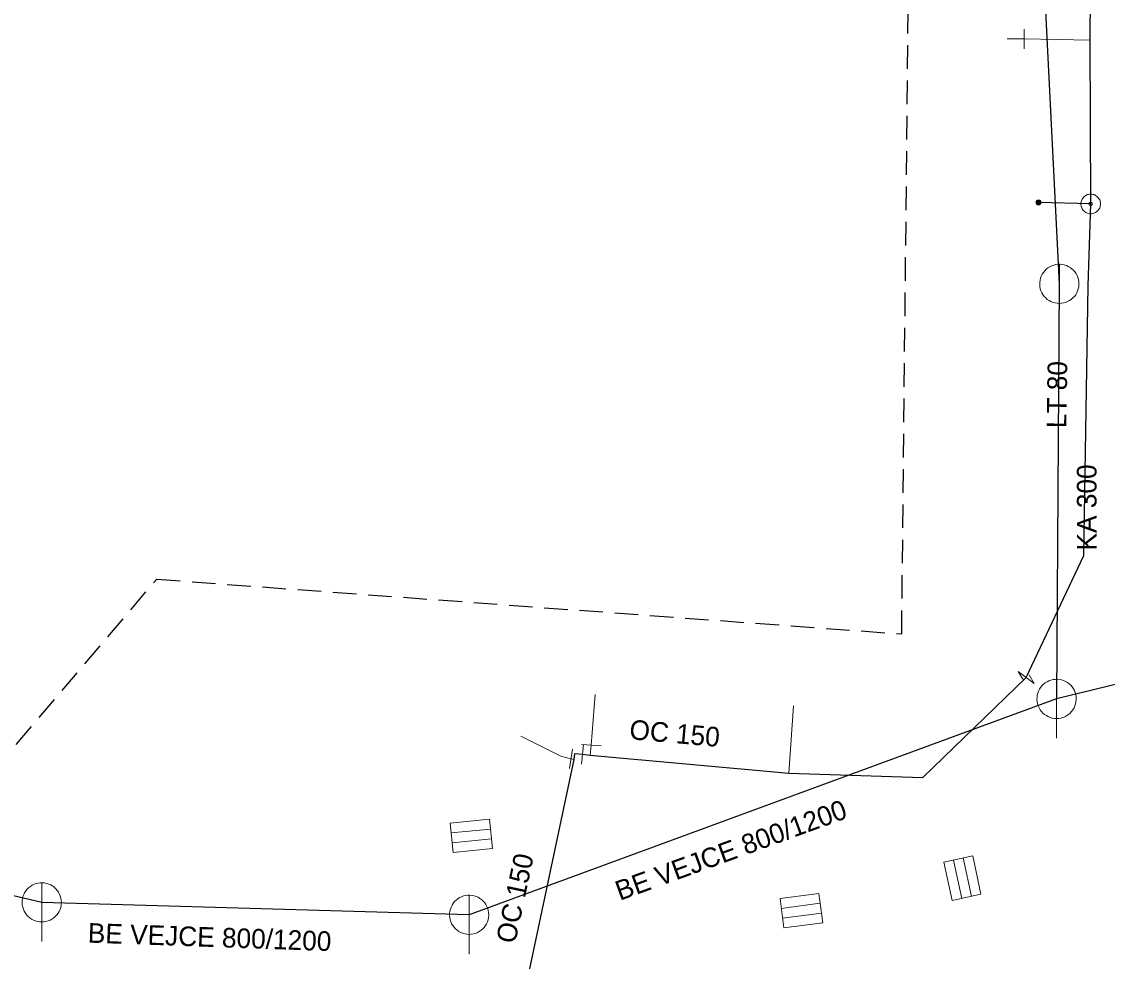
# Model space of a CAD drawing. Extents: x -725643 to -725418, y -978375 to -978221.
# Drawn here: x -725502 to -725446.7, y -978340.9 to -978293 of the extents above; entities that cross this region are included whole.
import ezdxf

# ---------------------------------------------------------------- set-up
doc = ezdxf.new("R2010")
doc.units = 0
doc.header["$LTSCALE"] = 0.4
doc.linetypes.add('MEDIUM_DASHED', pattern=[4.5, 3, -1.5])
doc.layers.add('1', color=7, linetype='Continuous')
for name, color, linetype, lineweight in [('13', 7, 'Continuous', 13), ('14', 7, 'Continuous', 25), ('17', 7, 'Continuous', 25), ('22', 7, 'Continuous', 13), ('34', 7, 'Continuous', 13), ('47', 7, 'Continuous', 13), ('63', 7, 'MEDIUM_DASHED', 25), ('9', 7, 'Continuous', 13)]:
    doc.layers.add(name, color=color, linetype=linetype, lineweight=lineweight)

msp = doc.modelspace()

# ---------------------------------------------------------------- linework, layer by layer
at = {"layer": '13'}
for p, q in [((-725450.884, -978293.877), (-725451.759, -978293.873)), ((-725447.519, -978293.935), (-725450.884, -978293.877)), ((-725462.878, -978331.295), (-725462.639, -978327.859))]:
    msp.add_line(p, q, dxfattribs=at)
for points in [[(-725473.014, -978330.373), (-725472.951, -978329.869), (-725472.749, -978327.278)], [(-725473.986, -978330.566), (-725474.5, -978330.421), (-725476.532, -978329.406)]]:
    msp.add_lwpolyline(points, dxfattribs=at)
at = {"layer": '14'}
for p, q in [((-725450.636, -978276.041), (-725449.097, -978306.355)), ((-725449.097, -978306.355), (-725449.237, -978327.509)), ((-725418.473, -978319.91), (-725449.237, -978327.509))]:
    msp.add_line(p, q, dxfattribs=at)
at = {"layer": '14', "lineweight": 13}
msp.add_line((-725473.829, -978330.592), (-725473.986, -978330.566), dxfattribs=at)
at = {"layer": '14'}
for points in [[(-725449.237, -978327.509), (-725479.175, -978338.51), (-725500.956, -978337.877)], [(-725500.956, -978337.877), (-725523.136, -978332.647), (-725524.855, -978332.647), (-725526.213, -978332.919), (-725527.118, -978333.688), (-725527.513, -978334.331)]]:
    msp.add_lwpolyline(points, dxfattribs=at)
at = {"layer": '17'}
for points in [[(-725447.498, -978302.284), (-725447.519, -978293.935), (-725447.498, -978289.33), (-725447.528, -978279.514), (-725448.234, -978269.846), (-725448.21, -978267.82), (-725448.151, -978262.699), (-725445.719, -978241.531), (-725443.089, -978227.013), (-725441.23, -978223.25), (-725440.059, -978221.699), (-725439.43, -978221.1), (-725439.089, -978220.568)], [(-725450.783, -978326.417), (-725447.845, -978320.194), (-725447.621, -978306.459), (-725447.498, -978302.284), (-725450.158, -978302.21)], [(-725473.397, -978330.332), (-725473.013, -978330.373), (-725462.877, -978331.295), (-725456.052, -978331.515), (-725450.783, -978326.417)], [(-725476.724, -978344.299), (-725473.829, -978330.592), (-725473.78, -978330.284), (-725473.397, -978330.332)]]:
    msp.add_lwpolyline(points, dxfattribs=at)
at = {"layer": '22'}
for p, q in [((-725449.097, -978308.355), (-725449.096, -978305.355)), ((-725449.237, -978329.509), (-725449.236, -978326.509)), ((-725480.082, -978334.342), (-725478.092, -978334.141)), ((-725480.032, -978334.84), (-725478.042, -978334.638)), ((-725454.489, -978335.722), (-725454.069, -978337.678)), ((-725454, -978335.617), (-725453.58, -978337.573)), ((-725500.956, -978339.877), (-725500.955, -978336.877)), ((-725479.175, -978340.51), (-725479.174, -978337.51)), ((-725463.265, -978338.184), (-725461.282, -978337.925)), ((-725463.201, -978338.68), (-725461.217, -978338.421))]:
    msp.add_line(p, q, dxfattribs=at)
for points in [[(-725448.097, -978306.355), (-725448.102, -978306.246), (-725448.12, -978306.138), (-725448.15, -978306.032), (-725448.19, -978305.931), (-725448.242, -978305.834), (-725448.304, -978305.744), (-725448.376, -978305.661), (-725448.456, -978305.587), (-725448.544, -978305.521), (-725448.638, -978305.466), (-725448.738, -978305.421), (-725448.843, -978305.388), (-725448.95, -978305.366), (-725449.059, -978305.356), (-725449.169, -978305.358), (-725449.277, -978305.372), (-725449.384, -978305.397), (-725449.487, -978305.434), (-725449.585, -978305.483), (-725449.677, -978305.541), (-725449.763, -978305.61), (-725449.84, -978305.687), (-725449.909, -978305.773), (-725449.968, -978305.865), (-725450.016, -978305.963), (-725450.053, -978306.066), (-725450.079, -978306.173), (-725450.093, -978306.281), (-725450.096, -978306.391), (-725450.086, -978306.5), (-725450.065, -978306.607), (-725450.031, -978306.711), (-725449.987, -978306.811), (-725449.932, -978306.906), (-725449.866, -978306.994), (-725449.792, -978307.074), (-725449.709, -978307.146), (-725449.619, -978307.208), (-725449.523, -978307.26), (-725449.421, -978307.301), (-725449.316, -978307.331), (-725449.208, -978307.349), (-725449.098, -978307.355), (-725448.989, -978307.349), (-725448.881, -978307.331), (-725448.776, -978307.302), (-725448.674, -978307.261), (-725448.577, -978307.209), (-725448.487, -978307.147), (-725448.404, -978307.076), (-725448.329, -978306.996), (-725448.264, -978306.908), (-725448.208, -978306.814), (-725448.164, -978306.714), (-725448.13, -978306.61), (-725448.108, -978306.502), (-725448.098, -978306.393)], [(-725448.237, -978327.509), (-725448.242, -978327.4), (-725448.26, -978327.292), (-725448.29, -978327.186), (-725448.33, -978327.085), (-725448.382, -978326.988), (-725448.444, -978326.898), (-725448.516, -978326.815), (-725448.596, -978326.741), (-725448.684, -978326.675), (-725448.778, -978326.62), (-725448.878, -978326.575), (-725448.983, -978326.542), (-725449.09, -978326.52), (-725449.199, -978326.51), (-725449.309, -978326.512), (-725449.417, -978326.526), (-725449.524, -978326.551), (-725449.627, -978326.588), (-725449.725, -978326.637), (-725449.817, -978326.695), (-725449.903, -978326.764), (-725449.98, -978326.841), (-725450.049, -978326.927), (-725450.108, -978327.019), (-725450.156, -978327.117), (-725450.193, -978327.22), (-725450.219, -978327.327), (-725450.233, -978327.435), (-725450.236, -978327.545), (-725450.226, -978327.654), (-725450.205, -978327.761), (-725450.171, -978327.865), (-725450.127, -978327.965), (-725450.072, -978328.06), (-725450.006, -978328.148), (-725449.932, -978328.228), (-725449.849, -978328.3), (-725449.759, -978328.362), (-725449.663, -978328.414), (-725449.561, -978328.455), (-725449.456, -978328.485), (-725449.348, -978328.503), (-725449.238, -978328.509), (-725449.129, -978328.503), (-725449.021, -978328.485), (-725448.916, -978328.456), (-725448.814, -978328.415), (-725448.717, -978328.363), (-725448.627, -978328.301), (-725448.544, -978328.23), (-725448.469, -978328.15), (-725448.404, -978328.062), (-725448.348, -978327.968), (-725448.304, -978327.868), (-725448.27, -978327.764), (-725448.248, -978327.656), (-725448.238, -978327.547)], [(-725480.133, -978333.845), (-725478.143, -978333.643), (-725477.992, -978335.135), (-725479.981, -978335.337)], [(-725453.511, -978335.512), (-725453.091, -978337.468), (-725454.558, -978337.783), (-725454.978, -978335.827)], [(-725499.956, -978337.877), (-725499.961, -978337.768), (-725499.979, -978337.66), (-725500.009, -978337.554), (-725500.049, -978337.453), (-725500.101, -978337.356), (-725500.163, -978337.266), (-725500.235, -978337.183), (-725500.315, -978337.109), (-725500.403, -978337.043), (-725500.497, -978336.988), (-725500.597, -978336.943), (-725500.702, -978336.91), (-725500.809, -978336.888), (-725500.918, -978336.878), (-725501.028, -978336.88), (-725501.136, -978336.894), (-725501.243, -978336.919), (-725501.346, -978336.956), (-725501.444, -978337.005), (-725501.536, -978337.063), (-725501.622, -978337.132), (-725501.699, -978337.209), (-725501.768, -978337.295), (-725501.827, -978337.387), (-725501.875, -978337.485), (-725501.912, -978337.588), (-725501.938, -978337.695), (-725501.952, -978337.803), (-725501.955, -978337.913), (-725501.945, -978338.022), (-725501.924, -978338.129), (-725501.89, -978338.233), (-725501.846, -978338.333), (-725501.791, -978338.428), (-725501.725, -978338.516), (-725501.651, -978338.596), (-725501.568, -978338.668), (-725501.478, -978338.73), (-725501.382, -978338.782), (-725501.28, -978338.823), (-725501.175, -978338.853), (-725501.067, -978338.871), (-725500.957, -978338.877), (-725500.848, -978338.871), (-725500.74, -978338.853), (-725500.635, -978338.824), (-725500.533, -978338.783), (-725500.436, -978338.731), (-725500.346, -978338.669), (-725500.263, -978338.598), (-725500.188, -978338.518), (-725500.123, -978338.43), (-725500.067, -978338.336), (-725500.023, -978338.236), (-725499.989, -978338.132), (-725499.967, -978338.024), (-725499.957, -978337.915)], [(-725478.175, -978338.51), (-725478.18, -978338.401), (-725478.198, -978338.293), (-725478.228, -978338.187), (-725478.268, -978338.086), (-725478.32, -978337.989), (-725478.382, -978337.899), (-725478.454, -978337.816), (-725478.534, -978337.742), (-725478.622, -978337.676), (-725478.716, -978337.621), (-725478.816, -978337.576), (-725478.921, -978337.543), (-725479.028, -978337.521), (-725479.137, -978337.511), (-725479.247, -978337.513), (-725479.355, -978337.527), (-725479.462, -978337.552), (-725479.565, -978337.589), (-725479.663, -978337.638), (-725479.755, -978337.696), (-725479.841, -978337.765), (-725479.918, -978337.842), (-725479.987, -978337.928), (-725480.046, -978338.02), (-725480.094, -978338.118), (-725480.131, -978338.221), (-725480.157, -978338.328), (-725480.171, -978338.436), (-725480.174, -978338.546), (-725480.164, -978338.655), (-725480.143, -978338.762), (-725480.109, -978338.866), (-725480.065, -978338.966), (-725480.01, -978339.061), (-725479.944, -978339.149), (-725479.87, -978339.229), (-725479.787, -978339.301), (-725479.697, -978339.363), (-725479.601, -978339.415), (-725479.499, -978339.456), (-725479.394, -978339.486), (-725479.286, -978339.504), (-725479.176, -978339.51), (-725479.067, -978339.504), (-725478.959, -978339.486), (-725478.854, -978339.457), (-725478.752, -978339.416), (-725478.655, -978339.364), (-725478.565, -978339.302), (-725478.482, -978339.231), (-725478.407, -978339.151), (-725478.342, -978339.063), (-725478.286, -978338.969), (-725478.242, -978338.869), (-725478.208, -978338.765), (-725478.186, -978338.657), (-725478.176, -978338.548)], [(-725463.33, -978337.688), (-725461.347, -978337.429), (-725461.153, -978338.917), (-725463.136, -978339.175)]]:
    msp.add_lwpolyline(points, close=True, dxfattribs=at)
at = {"layer": '34'}
for p, q in [((-725450.881, -978293.377), (-725450.887, -978294.376)), ((-725473.91, -978330.071), (-725474.062, -978331.06)), ((-725473.449, -978329.829), (-725472.452, -978329.907)), ((-725473.345, -978329.834), (-725473.449, -978330.829))]:
    msp.add_line(p, q, dxfattribs=at)
at = {"layer": '47'}
msp.add_line((-725451.193, -978326.115), (-725450.93, -978326.553), dxfattribs=at)
for points in [[(-725446.998, -978302.284), (-725447.001, -978302.232), (-725447.009, -978302.179), (-725447.023, -978302.13), (-725447.041, -978302.081), (-725447.065, -978302.034), (-725447.094, -978301.99), (-725447.127, -978301.95), (-725447.164, -978301.913), (-725447.204, -978301.88), (-725447.248, -978301.851), (-725447.295, -978301.826), (-725447.344, -978301.809), (-725447.394, -978301.795), (-725447.446, -978301.787), (-725447.498, -978301.784), (-725447.55, -978301.787), (-725447.602, -978301.795), (-725447.653, -978301.809), (-725447.701, -978301.826), (-725447.748, -978301.851), (-725447.792, -978301.88), (-725447.833, -978301.913), (-725447.87, -978301.95), (-725447.903, -978301.99), (-725447.931, -978302.034), (-725447.955, -978302.081), (-725447.974, -978302.13), (-725447.987, -978302.179), (-725447.995, -978302.232), (-725447.998, -978302.284), (-725447.995, -978302.336), (-725447.987, -978302.388), (-725447.974, -978302.439), (-725447.955, -978302.487), (-725447.931, -978302.534), (-725447.903, -978302.578), (-725447.87, -978302.619), (-725447.833, -978302.656), (-725447.792, -978302.689), (-725447.748, -978302.717), (-725447.701, -978302.741), (-725447.653, -978302.76), (-725447.602, -978302.772), (-725447.55, -978302.781), (-725447.498, -978302.784), (-725447.446, -978302.781), (-725447.394, -978302.772), (-725447.344, -978302.76), (-725447.295, -978302.741), (-725447.248, -978302.717), (-725447.204, -978302.689), (-725447.164, -978302.656), (-725447.127, -978302.619), (-725447.094, -978302.578), (-725447.065, -978302.534), (-725447.041, -978302.487), (-725447.023, -978302.439), (-725447.009, -978302.388), (-725447.001, -978302.336)], [(-725447.416, -978302.284), (-725447.416, -978302.275), (-725447.418, -978302.267), (-725447.42, -978302.259), (-725447.423, -978302.25), (-725447.427, -978302.243), (-725447.432, -978302.236), (-725447.437, -978302.228), (-725447.443, -978302.223), (-725447.45, -978302.218), (-725447.457, -978302.213), (-725447.465, -978302.209), (-725447.473, -978302.206), (-725447.481, -978302.204), (-725447.489, -978302.201), (-725447.498, -978302.201), (-725447.507, -978302.201), (-725447.515, -978302.204), (-725447.523, -978302.206), (-725447.531, -978302.209), (-725447.539, -978302.213), (-725447.546, -978302.218), (-725447.553, -978302.223), (-725447.559, -978302.228), (-725447.565, -978302.236), (-725447.569, -978302.243), (-725447.573, -978302.25), (-725447.576, -978302.259), (-725447.578, -978302.267), (-725447.58, -978302.275), (-725447.58, -978302.284), (-725447.58, -978302.293), (-725447.578, -978302.301), (-725447.576, -978302.309), (-725447.573, -978302.317), (-725447.569, -978302.325), (-725447.565, -978302.331), (-725447.559, -978302.339), (-725447.553, -978302.345), (-725447.546, -978302.351), (-725447.539, -978302.355), (-725447.531, -978302.358), (-725447.523, -978302.362), (-725447.515, -978302.364), (-725447.507, -978302.366), (-725447.498, -978302.366), (-725447.489, -978302.366), (-725447.481, -978302.364), (-725447.473, -978302.362), (-725447.465, -978302.358), (-725447.457, -978302.355), (-725447.45, -978302.351), (-725447.443, -978302.345), (-725447.437, -978302.339), (-725447.432, -978302.331), (-725447.427, -978302.325), (-725447.423, -978302.317), (-725447.42, -978302.309), (-725447.418, -978302.301), (-725447.416, -978302.293)]]:
    msp.add_lwpolyline(points, close=True, dxfattribs=at)
msp.add_lwpolyline([(-725451.193, -978326.115), (-725450.372, -978326.718), (-725450.635, -978326.28)], dxfattribs=at)
at = {"layer": '63'}
msp.add_lwpolyline([(-725504.582, -978332.573), (-725495.092, -978321.408), (-725495.092, -978321.408), (-725457.131, -978324.199), (-725457.131, -978324.199), (-725456.573, -978271.166), (-725456.573, -978271.166), (-725442.617, -978268.933), (-725442.617, -978268.933), (-725440.663, -978348.762), (-725440.663, -978348.762), (-725504.582, -978352.39)], dxfattribs=at)
at = {"layer": '9'}
for points in [[(-725450.284, -978302.21), (-725450.284, -978302.223), (-725450.282, -978302.236), (-725450.279, -978302.249), (-725450.274, -978302.261), (-725450.268, -978302.273), (-725450.261, -978302.284), (-725450.253, -978302.294), (-725450.243, -978302.304), (-725450.233, -978302.312), (-725450.222, -978302.319), (-725450.21, -978302.325), (-725450.198, -978302.33), (-725450.185, -978302.333), (-725450.172, -978302.335), (-725450.159, -978302.337), (-725450.146, -978302.336), (-725450.133, -978302.334), (-725450.12, -978302.331), (-725450.108, -978302.326), (-725450.096, -978302.32), (-725450.085, -978302.313), (-725450.075, -978302.305), (-725450.065, -978302.295), (-725450.057, -978302.285), (-725450.05, -978302.274), (-725450.044, -978302.262), (-725450.039, -978302.25), (-725450.036, -978302.237), (-725450.034, -978302.224), (-725450.032, -978302.211), (-725450.033, -978302.198), (-725450.035, -978302.185), (-725450.038, -978302.172), (-725450.043, -978302.16), (-725450.049, -978302.148), (-725450.056, -978302.137), (-725450.064, -978302.127), (-725450.074, -978302.117), (-725450.084, -978302.109), (-725450.095, -978302.102), (-725450.107, -978302.096), (-725450.119, -978302.091), (-725450.132, -978302.088), (-725450.145, -978302.086), (-725450.158, -978302.085), (-725450.171, -978302.085), (-725450.184, -978302.087), (-725450.197, -978302.09), (-725450.209, -978302.095), (-725450.221, -978302.101), (-725450.232, -978302.108), (-725450.242, -978302.116), (-725450.252, -978302.126), (-725450.26, -978302.136), (-725450.267, -978302.147), (-725450.273, -978302.159), (-725450.278, -978302.171), (-725450.281, -978302.184), (-725450.283, -978302.197)], [(-725450.264, -978302.21), (-725450.265, -978302.221), (-725450.263, -978302.232), (-725450.26, -978302.243), (-725450.256, -978302.253), (-725450.251, -978302.263), (-725450.245, -978302.272), (-725450.238, -978302.281), (-725450.23, -978302.289), (-725450.221, -978302.296), (-725450.212, -978302.302), (-725450.202, -978302.307), (-725450.192, -978302.311), (-725450.181, -978302.314), (-725450.17, -978302.317), (-725450.159, -978302.317), (-725450.148, -978302.317), (-725450.137, -978302.315), (-725450.126, -978302.312), (-725450.116, -978302.308), (-725450.106, -978302.303), (-725450.097, -978302.297), (-725450.088, -978302.29), (-725450.08, -978302.282), (-725450.073, -978302.273), (-725450.067, -978302.264), (-725450.062, -978302.254), (-725450.058, -978302.244), (-725450.055, -978302.233), (-725450.053, -978302.222), (-725450.052, -978302.211), (-725450.052, -978302.2), (-725450.054, -978302.189), (-725450.057, -978302.178), (-725450.061, -978302.168), (-725450.066, -978302.158), (-725450.072, -978302.149), (-725450.079, -978302.14), (-725450.087, -978302.132), (-725450.096, -978302.125), (-725450.105, -978302.119), (-725450.115, -978302.114), (-725450.125, -978302.11), (-725450.136, -978302.107), (-725450.147, -978302.105), (-725450.158, -978302.105), (-725450.169, -978302.104), (-725450.18, -978302.106), (-725450.191, -978302.109), (-725450.201, -978302.113), (-725450.211, -978302.118), (-725450.22, -978302.124), (-725450.229, -978302.131), (-725450.237, -978302.139), (-725450.244, -978302.148), (-725450.25, -978302.157), (-725450.255, -978302.167), (-725450.259, -978302.177), (-725450.262, -978302.188), (-725450.264, -978302.199)], [(-725450.245, -978302.21), (-725450.245, -978302.219), (-725450.244, -978302.228), (-725450.241, -978302.237), (-725450.238, -978302.245), (-725450.234, -978302.253), (-725450.229, -978302.261), (-725450.223, -978302.268), (-725450.217, -978302.274), (-725450.21, -978302.28), (-725450.202, -978302.285), (-725450.194, -978302.289), (-725450.186, -978302.292), (-725450.177, -978302.295), (-725450.168, -978302.296), (-725450.159, -978302.298), (-725450.15, -978302.297), (-725450.141, -978302.296), (-725450.132, -978302.293), (-725450.124, -978302.29), (-725450.116, -978302.286), (-725450.108, -978302.281), (-725450.101, -978302.275), (-725450.095, -978302.269), (-725450.089, -978302.262), (-725450.084, -978302.254), (-725450.08, -978302.246), (-725450.077, -978302.238), (-725450.074, -978302.229), (-725450.073, -978302.22), (-725450.071, -978302.211), (-725450.072, -978302.202), (-725450.073, -978302.193), (-725450.076, -978302.184), (-725450.079, -978302.176), (-725450.083, -978302.168), (-725450.088, -978302.16), (-725450.094, -978302.153), (-725450.1, -978302.147), (-725450.107, -978302.141), (-725450.115, -978302.136), (-725450.123, -978302.132), (-725450.131, -978302.129), (-725450.14, -978302.126), (-725450.149, -978302.125), (-725450.158, -978302.124), (-725450.167, -978302.124), (-725450.176, -978302.125), (-725450.185, -978302.128), (-725450.193, -978302.131), (-725450.201, -978302.135), (-725450.209, -978302.14), (-725450.216, -978302.146), (-725450.222, -978302.152), (-725450.228, -978302.159), (-725450.233, -978302.167), (-725450.237, -978302.175), (-725450.24, -978302.183), (-725450.243, -978302.192), (-725450.244, -978302.201)], [(-725450.225, -978302.21), (-725450.225, -978302.217), (-725450.224, -978302.224), (-725450.223, -978302.231), (-725450.22, -978302.237), (-725450.217, -978302.243), (-725450.213, -978302.249), (-725450.209, -978302.255), (-725450.204, -978302.26), (-725450.198, -978302.264), (-725450.192, -978302.268), (-725450.186, -978302.271), (-725450.18, -978302.274), (-725450.173, -978302.275), (-725450.166, -978302.278), (-725450.159, -978302.278), (-725450.152, -978302.278), (-725450.145, -978302.276), (-725450.138, -978302.275), (-725450.132, -978302.272), (-725450.125, -978302.269), (-725450.12, -978302.265), (-725450.114, -978302.261), (-725450.109, -978302.256), (-725450.105, -978302.25), (-725450.101, -978302.244), (-725450.098, -978302.238), (-725450.095, -978302.232), (-725450.093, -978302.225), (-725450.092, -978302.218), (-725450.091, -978302.211), (-725450.091, -978302.204), (-725450.092, -978302.197), (-725450.094, -978302.19), (-725450.097, -978302.184), (-725450.1, -978302.177), (-725450.104, -978302.172), (-725450.108, -978302.166), (-725450.113, -978302.161), (-725450.119, -978302.157), (-725450.124, -978302.153), (-725450.131, -978302.15), (-725450.137, -978302.147), (-725450.144, -978302.145), (-725450.151, -978302.144), (-725450.158, -978302.144), (-725450.165, -978302.144), (-725450.172, -978302.144), (-725450.179, -978302.146), (-725450.185, -978302.149), (-725450.191, -978302.152), (-725450.197, -978302.156), (-725450.203, -978302.16), (-725450.208, -978302.165), (-725450.212, -978302.171), (-725450.216, -978302.176), (-725450.219, -978302.183), (-725450.222, -978302.189), (-725450.223, -978302.196), (-725450.225, -978302.203)], [(-725450.205, -978302.21), (-725450.205, -978302.215), (-725450.205, -978302.22), (-725450.204, -978302.225), (-725450.202, -978302.229), (-725450.2, -978302.234), (-725450.197, -978302.238), (-725450.194, -978302.241), (-725450.19, -978302.245), (-725450.187, -978302.248), (-725450.183, -978302.251), (-725450.178, -978302.253), (-725450.174, -978302.255), (-725450.169, -978302.256), (-725450.164, -978302.258), (-725450.159, -978302.258), (-725450.154, -978302.258), (-725450.149, -978302.257), (-725450.144, -978302.256), (-725450.14, -978302.254), (-725450.135, -978302.252), (-725450.131, -978302.249), (-725450.127, -978302.246), (-725450.124, -978302.242), (-725450.121, -978302.239), (-725450.118, -978302.235), (-725450.116, -978302.23), (-725450.114, -978302.226), (-725450.113, -978302.221), (-725450.112, -978302.216), (-725450.111, -978302.211), (-725450.111, -978302.206), (-725450.112, -978302.201), (-725450.113, -978302.196), (-725450.115, -978302.192), (-725450.117, -978302.187), (-725450.12, -978302.183), (-725450.123, -978302.179), (-725450.126, -978302.176), (-725450.13, -978302.173), (-725450.134, -978302.17), (-725450.139, -978302.168), (-725450.143, -978302.166), (-725450.148, -978302.165), (-725450.153, -978302.164), (-725450.158, -978302.164), (-725450.163, -978302.164), (-725450.168, -978302.165), (-725450.173, -978302.165), (-725450.177, -978302.167), (-725450.182, -978302.169), (-725450.186, -978302.172), (-725450.189, -978302.175), (-725450.193, -978302.178), (-725450.196, -978302.182), (-725450.199, -978302.186), (-725450.201, -978302.191), (-725450.203, -978302.195), (-725450.204, -978302.2), (-725450.205, -978302.205)], [(-725450.185, -978302.21), (-725450.185, -978302.213), (-725450.186, -978302.216), (-725450.185, -978302.218), (-725450.184, -978302.221), (-725450.183, -978302.224), (-725450.181, -978302.226), (-725450.179, -978302.228), (-725450.177, -978302.23), (-725450.175, -978302.232), (-725450.173, -978302.234), (-725450.17, -978302.236), (-725450.167, -978302.237), (-725450.165, -978302.237), (-725450.162, -978302.238), (-725450.159, -978302.238), (-725450.156, -978302.238), (-725450.153, -978302.238), (-725450.15, -978302.237), (-725450.148, -978302.236), (-725450.145, -978302.235), (-725450.143, -978302.233), (-725450.14, -978302.231), (-725450.138, -978302.229), (-725450.137, -978302.227), (-725450.135, -978302.225), (-725450.134, -978302.222), (-725450.132, -978302.219), (-725450.132, -978302.217), (-725450.131, -978302.214), (-725450.13, -978302.211), (-725450.131, -978302.208), (-725450.131, -978302.205), (-725450.132, -978302.202), (-725450.133, -978302.2), (-725450.134, -978302.197), (-725450.136, -978302.195), (-725450.137, -978302.192), (-725450.139, -978302.19), (-725450.142, -978302.189), (-725450.144, -978302.187), (-725450.147, -978302.186), (-725450.149, -978302.185), (-725450.152, -978302.184), (-725450.155, -978302.184), (-725450.158, -978302.183), (-725450.161, -978302.184), (-725450.164, -978302.183), (-725450.166, -978302.185), (-725450.169, -978302.185), (-725450.172, -978302.186), (-725450.174, -978302.188), (-725450.176, -978302.189), (-725450.178, -978302.191), (-725450.18, -978302.194), (-725450.182, -978302.196), (-725450.183, -978302.199), (-725450.184, -978302.201), (-725450.185, -978302.204), (-725450.185, -978302.207)], [(-725450.166, -978302.21), (-725450.166, -978302.212), (-725450.166, -978302.212), (-725450.165, -978302.212), (-725450.165, -978302.214), (-725450.166, -978302.215), (-725450.164, -978302.215), (-725450.164, -978302.215), (-725450.164, -978302.217), (-725450.164, -978302.217), (-725450.163, -978302.218), (-725450.161, -978302.218), (-725450.161, -978302.218), (-725450.161, -978302.219), (-725450.159, -978302.219), (-725450.159, -978302.219), (-725450.158, -978302.219), (-725450.157, -978302.219), (-725450.157, -978302.218), (-725450.156, -978302.218), (-725450.154, -978302.218), (-725450.154, -978302.217), (-725450.154, -978302.217), (-725450.153, -978302.216), (-725450.153, -978302.216), (-725450.151, -978302.215), (-725450.151, -978302.214), (-725450.15, -978302.213), (-725450.15, -978302.213), (-725450.15, -978302.212), (-725450.15, -978302.211), (-725450.15, -978302.21), (-725450.15, -978302.209), (-725450.15, -978302.209), (-725450.151, -978302.208), (-725450.151, -978302.207), (-725450.152, -978302.206), (-725450.152, -978302.206), (-725450.153, -978302.205), (-725450.153, -978302.205), (-725450.154, -978302.204), (-725450.155, -978302.204), (-725450.156, -978302.203), (-725450.156, -978302.203), (-725450.157, -978302.203), (-725450.158, -978302.203), (-725450.159, -978302.203), (-725450.16, -978302.203), (-725450.16, -978302.203), (-725450.161, -978302.204), (-725450.162, -978302.203), (-725450.163, -978302.205), (-725450.163, -978302.205), (-725450.164, -978302.205), (-725450.164, -978302.205), (-725450.165, -978302.207), (-725450.165, -978302.208), (-725450.165, -978302.209), (-725450.166, -978302.209), (-725450.166, -978302.21)]]:
    msp.add_lwpolyline(points, close=True, dxfattribs=at)

# ---------------------------------------------------------------- texts
at = {"layer": '1'}
for s, rotation, p in [('LT 80 ', 89, (-725448.747, -978313.719)), ('KA 300', 90, (-725447.2, -978319.944)), ('OC 150', 355, (-725471.035, -978329.558)), ('BE VEJCE 800/1200 ', 20, (-725471.498, -978337.804)), ('OC 150', 78, (-725476.833, -978340.024)), ('BE VEJCE 800/1200 ', 358, (-725498.619, -978339.93))]:
    msp.add_text(s, height=1, rotation=rotation, dxfattribs=at).set_placement(p)

doc.saveas('drawing.dxf')
